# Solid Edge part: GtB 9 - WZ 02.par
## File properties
Author: Carsten
Template: Normal.par
Last saved by: Carsten
Revision: 2
Application: Solid Edge
Genauigkeit: 0,990
Teilflächenrmatvorlage: Model Default
Coef. of Thermal Exp: 0.0
Thermal Conductivity: 0.0
Specific Heat: 0.0
Modulus of Elasticity: 0.0
Poission's Ratio: 0.0
Yield Stress: 0.0
Ultimate Stress: 0.0
Elongation: 0.0
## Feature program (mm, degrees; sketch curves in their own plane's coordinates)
sketch for "unnamed Protrusion 1" plane through (0, 0, 0) normal (1, 0, 0) x-axis (0, 1, 0)
  line (-24.8277, 40.9595) -> (50.1723, 40.9595)
  line (50.1723, 40.9595) -> (50.1723, -19.0405)
  line (50.1723, -19.0405) -> (-24.8277, -19.0405)
  line (-24.8277, -19.0405) -> (-24.8277, 40.9595)
extrude "unnamed Protrusion 1" add finite 45 along -normal
sketch for "Ausschnitt_1" plane through (0, 12.6723, 10.9595) normal (1, 0, 0) x-axis (0, 1, 0)
  line (-17.5, -30) -> (-17.5, -25)
  line (-17.5, -25) -> (32.5, -25)
  line (32.5, -25) -> (32.5, -30)
  line (32.5, -30) -> (-17.5, -30)
  dimension (linear) = 17.5
  dimension (linear) = 17.5
  dimension (linear) = 32.5
extrude "Ausschnitt_1" cut finite 85.725 along -normal
sketch for "Ausschnitt_2" plane through (-22.5, -14.8277, -19.0405) normal (0, 0, -1) x-axis (1, 0, 0)
  line (-7.5, 5) -> (7.5, 5)
  line (7.5, 5) -> (7.5, -5)
  line (7.5, -5) -> (-7.5, -5)
  line (-7.5, -5) -> (-7.5, 5)
  dimension (linear) = 7.5
  dimension (linear) = 7.5
extrude "Ausschnitt_2" cut finite 104.775 along -normal
sketch for "Ausschnitt_3" #1 plane through (-22.5, -24.8277, 10.9595) normal (0, -1, 0) x-axis (1, 0, 0)
  line (22.5, 25) -> (17.5, 25)
  line (17.5, 25) -> (17.5, -15)
  line (17.5, -15) -> (22.5, -15)
  line (22.5, -15) -> (22.5, 25)
sketch for "Ausschnitt_3" #2 plane through (-22.5, -24.8277, 10.9595) normal (0, -1, 0) x-axis (1, 0, 0)
  line (-22.5, 25) -> (-17.5, 25)
  line (-17.5, 25) -> (-17.5, -15)
  line (-17.5, -15) -> (-22.5, -15)
  line (-22.5, -15) -> (-22.5, 25)
  dimension (linear) = 22.5
  dimension (linear) = 22.5
  dimension (linear) = 22.5
  dimension (linear) = 22.5
extrude "Ausschnitt_3" cut finite 82.55 along -normal
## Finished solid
Body 1: solid body, 22 faces, 60 edges, 40 vertices.
  Faces by surface: plane 22
  Edges by curve: line 60
Bounding box of the edges (mm): 45.000 x 75.000 x 60.000, from (-45, -24.8277, -19.0405) to (0, 50.1723, 40.9595).
Planar faces by outward normal: +x 4, +y 3, +z 3, -x 4, -y 3, -z 5
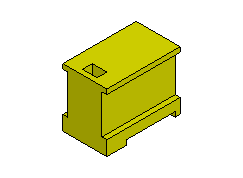
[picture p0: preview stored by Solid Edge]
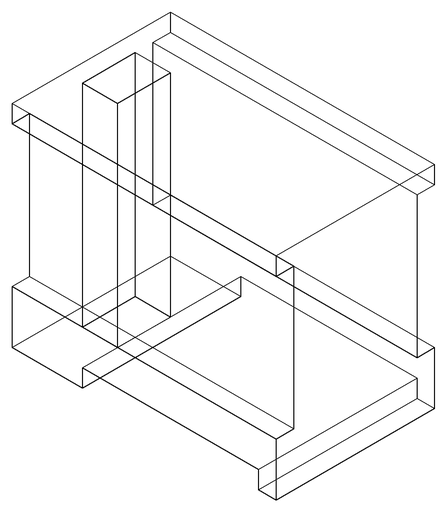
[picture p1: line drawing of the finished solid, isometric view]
